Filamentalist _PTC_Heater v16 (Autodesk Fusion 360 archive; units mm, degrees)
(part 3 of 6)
sketch "Sketch166" plane through (-12.9087, 0, 0) normal (-1, 0, 0) x axis (0, -1, 0)
  line L1 (-124.3873, 24.4213) -> (-76.1273, 24.4213)
  line L2 (-124.3873, 53.6313) -> (-124.3873, 24.4213)
  line L3 (-76.1273, 53.6313) -> (-124.3873, 53.6313)
  line L4 (-76.1273, 24.4213) -> (-76.1273, 53.6313)
  line L5 (-72.0887, 73.7538) -> (-72.0887, -226.7462)
  line L6 (-127.2387, 73.7538) -> (-72.0887, 73.7538)
  line L7 (-127.2387, -226.7462) -> (-127.2387, 73.7538)
  line L8 (-72.0887, -226.7462) -> (-127.2387, -226.7462)
  curve K1 (-89.2728, -182.9578) -> (-90.2131, -183.7393)
  line L9 (-87.8074, -183.1531) -> (-89.2728, -182.9578)
  curve K2 (-90.21, -184.8139) -> (-87.8074, -183.1531)
  curve K3 (-92.341, -183.8736) -> (-90.21, -184.8139)
  curve K4 (-92.8874, -181.9732) -> (-92.341, -183.8736)
  curve K5 (-90.3459, -179.0501) -> (-92.8874, -181.9732)
  curve K6 (-87.7097, -182.3716) -> (-90.3459, -179.0501)
  line L10 (-91.422, -182.3716) -> (-87.7097, -182.3716)
  curve K7 (-90.2131, -183.7393) -> (-91.422, -182.3716)
  curve K8 (-107.639, -181.8541) -> (-104.8013, -184.8139)
  curve K9 (-104.8105, -179.0501) -> (-107.639, -181.8541)
  curve K10 (-101.9728, -181.9167) -> (-104.8105, -179.0501)
  curve K11 (-104.8013, -184.8139) -> (-101.9728, -181.9167)
  line L11 (-84.5836, -127.5662) -> (-84.5836, -125.9146)
  line L12 (-86.049, -127.5662) -> (-84.5836, -127.5662)
  line L13 (-86.049, -121.9978) -> (-86.049, -127.5662)
  line L14 (-84.5836, -121.9978) -> (-86.049, -121.9978)
  line L15 (-84.5836, -122.7747) -> (-84.5836, -121.9978)
  curve K12 (-83.4769, -121.9001) -> (-84.5836, -122.7747)
  curve K13 (-82.6297, -122.2084) -> (-83.4769, -121.9001)
  line L16 (-82.9717, -123.6021) -> (-82.6297, -122.2084)
  curve K14 (-83.6372, -123.3655) -> (-82.9717, -123.6021)
  curve K15 (-84.5836, -125.9146) -> (-83.6372, -123.3655)
  line L17 (-92.7897, -121.9978) -> (-93.8644, -121.9978)
  line L18 (-92.7897, -123.0724) -> (-92.7897, -121.9978)
  line L19 (-93.8644, -123.0724) -> (-92.7897, -123.0724)
  line L20 (-93.8644, -125.4658) -> (-93.8644, -123.0724)
  curve K16 (-93.4461, -126.5893) -> (-93.8644, -125.4658)
  curve K17 (-92.8386, -126.4489) -> (-93.4461, -126.5893)
  line L21 (-92.692, -127.4701) -> (-92.8386, -126.4489)
  curve K18 (-93.8705, -127.6639) -> (-92.692, -127.4701)
  curve K19 (-95.2824, -126.5939) -> (-93.8705, -127.6639)
  curve K20 (-95.3297, -125.5391) -> (-95.2824, -126.5939)
  line L22 (-95.3297, -123.0724) -> (-95.3297, -125.5391)
  line L23 (-96.0136, -123.0724) -> (-95.3297, -123.0724)
  line L24 (-96.0136, -121.9978) -> (-96.0136, -123.0724)
  line L25 (-95.3297, -121.9978) -> (-96.0136, -121.9978)
  line L26 (-95.3297, -120.9231) -> (-95.3297, -121.9978)
  line L27 (-93.8644, -120.0439) -> (-95.3297, -120.9231)
  line L28 (-93.8644, -121.9978) -> (-93.8644, -120.0439)
  curve K21 (-104.0244, -125.8078) -> (-104.9646, -126.5893)
  line L29 (-102.559, -126.0031) -> (-104.0244, -125.8078)
  curve K22 (-104.9616, -127.6639) -> (-102.559, -126.0031)
  curve K23 (-107.0925, -126.7236) -> (-104.9616, -127.6639)
  curve K24 (-107.639, -124.8232) -> (-107.0925, -126.7236)
  curve K25 (-105.0974, -121.9001) -> (-107.639, -124.8232)
  curve K26 (-102.4613, -125.2216) -> (-105.0974, -121.9001)
  line L30 (-106.1736, -125.2216) -> (-102.4613, -125.2216)
  curve K27 (-104.9646, -126.5893) -> (-106.1736, -125.2216)
  line L31 (-114.7705, -127.5662) -> (-113.3051, -127.5662)
  line L32 (-114.7705, -119.9462) -> (-114.7705, -127.5662)
  line L33 (-113.3051, -119.9462) -> (-114.7705, -119.9462)
  line L34 (-113.3051, -122.9747) -> (-113.3051, -119.9462)
  line L35 (-110.179, -122.9747) -> (-113.3051, -122.9747)
  line L36 (-110.179, -119.9462) -> (-110.179, -122.9747)
  line L37 (-108.7136, -119.9462) -> (-110.179, -119.9462)
  line L38 (-108.7136, -127.5662) -> (-108.7136, -119.9462)
  line L39 (-110.179, -127.5662) -> (-108.7136, -127.5662)
  line L40 (-110.179, -124.2447) -> (-110.179, -127.5662)
  line L41 (-113.3051, -124.2447) -> (-110.179, -124.2447)
  line L42 (-113.3051, -127.5662) -> (-113.3051, -124.2447)
  curve K28 (-100.312, -123.6585) -> (-99.3992, -122.9747)
  line L43 (-101.582, -123.4631) -> (-100.312, -123.6585)
  curve K29 (-99.2527, -121.9001) -> (-101.582, -123.4631)
  curve K30 (-96.9905, -124.034) -> (-99.2527, -121.9001)
  line L44 (-96.9905, -125.7452) -> (-96.9905, -124.034)
  curve K31 (-96.5997, -127.5662) -> (-96.9905, -125.7452)
  line L45 (-98.0651, -127.5662) -> (-96.5997, -127.5662)
  curve K32 (-98.204, -127.0991) -> (-98.0651, -127.5662)
  curve K33 (-98.2559, -126.9144) -> (-98.204, -127.0991)
  curve K34 (-99.9549, -127.6639) -> (-98.2559, -126.9144)
  curve K35 (-101.7774, -125.9955) -> (-99.9549, -127.6639)
  curve K36 (-99.8297, -124.2203) -> (-101.7774, -125.9955)
  curve K37 (-98.4559, -123.8539) -> (-99.8297, -124.2203)
  line L46 (-98.4559, -123.715) -> (-98.4559, -123.8539)
  curve K38 (-99.3992, -122.9747) -> (-98.4559, -123.715)
  curve K39 (-88.7844, -125.8078) -> (-89.7246, -126.5893)
  line L47 (-87.319, -126.0031) -> (-88.7844, -125.8078)
  curve K40 (-89.7216, -127.6639) -> (-87.319, -126.0031)
  curve K41 (-91.8525, -126.7236) -> (-89.7216, -127.6639)
  curve K42 (-92.399, -124.8232) -> (-91.8525, -126.7236)
  curve K43 (-89.8574, -121.9001) -> (-92.399, -124.8232)
  curve K44 (-87.2213, -125.2216) -> (-89.8574, -121.9001)
  line L48 (-90.9336, -125.2216) -> (-87.2213, -125.2216)
  curve K45 (-89.7246, -126.5893) -> (-90.9336, -125.2216)
  line L49 (-114.282, -184.7162) -> (-112.8167, -184.7162)
  line L50 (-114.282, -177.0962) -> (-114.282, -184.7162)
  line L51 (-111.8443, -177.0962) -> (-114.282, -177.0962)
  curve K46 (-110.037, -177.2122) -> (-111.8443, -177.0962)
  curve K47 (-108.5182, -179.4607) -> (-110.037, -177.2122)
  curve K48 (-110.2171, -181.7732) -> (-108.5182, -179.4607)
  curve K49 (-111.8138, -181.8831) -> (-110.2171, -181.7732)
  line L52 (-112.8167, -181.8831) -> (-111.8138, -181.8831)
  line L53 (-112.8167, -184.7162) -> (-112.8167, -181.8831)
  line L54 (-99.8083, -184.7162) -> (-98.3735, -184.7162)
  line L55 (-101.582, -179.1478) -> (-99.8083, -184.7162)
  line L56 (-100.1411, -179.1478) -> (-101.582, -179.1478)
  line L57 (-99.0909, -182.7975) -> (-100.1411, -179.1478)
  line L58 (-98.1323, -179.1478) -> (-99.0909, -182.7975)
  line L59 (-96.7051, -179.1478) -> (-98.1323, -179.1478)
  line L60 (-95.7694, -182.7975) -> (-96.7051, -179.1478)
  line L61 (-94.7161, -179.1478) -> (-95.7694, -182.7975)
  line L62 (-93.2782, -179.1478) -> (-94.7161, -179.1478)
  line L63 (-95.0473, -184.7162) -> (-93.2782, -179.1478)
  line L64 (-96.4624, -184.7162) -> (-95.0473, -184.7162)
  line L65 (-97.4301, -181.1352) -> (-96.4624, -184.7162)
  line L66 (-98.3735, -184.7162) -> (-97.4301, -181.1352)
  line L67 (-85.072, -184.7162) -> (-85.072, -183.0646)
  line L68 (-86.5374, -184.7162) -> (-85.072, -184.7162)
  line L69 (-86.5374, -179.1478) -> (-86.5374, -184.7162)
  line L70 (-85.072, -179.1478) -> (-86.5374, -179.1478)
  line L71 (-85.072, -179.9247) -> (-85.072, -179.1478)
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  point P98 (-114.282, -184.7162)
  point P130 (-114.282, -184.7162)
  point P133 (-114.282, -70)
  coincident P98 P130
  coincident P133
  dimension "d521" Text1-Height = 9
extrude "Extrude53" new body sketch "Sketch166" along normal blind 0.5
move "Move16"
sketch "Sketch167" plane through (-13.4087, 0, 0) normal (-1, 0, 0) x axis (0, -1, 0)
  line L1 (-107.8677, -67.4885) -> (-114.2033, -67.4885)
  line L2 (-107.8677, -65.9722) -> (-107.8677, -67.4885)
  line L3 (-112.3861, -65.9722) -> (-107.8677, -65.9722)
  line L4 (-112.3861, -58.5622) -> (-112.3861, -65.9722)
  line L5 (-114.2033, -58.5622) -> (-112.3861, -58.5622)
  line L6 (-114.2033, -67.4885) -> (-114.2033, -58.5622)
extrude "Extrude54" cut sketch "Sketch167" against normal blind 1
component_insert "Component Insert17"
position "Position9"
sketch "Sketch168" plane through (0, 131.7787, 0) normal (0, 1, 0) x axis (-1, 0, 0)
  line L1 (-118.8314, -119.7) -> (-123.5512, -119.7)
  line L2 (-126.1913, -226.7462) -> (-126.1913, -119.7)
  line L3 (5.4087, -246.7462) -> (-106.1913, -246.7462)
  line L4 (25.4087, -119.7) -> (25.4087, -226.7462)
  line L5 (25.409, -119.7) -> (25.4087, -119.7)
  line L6 (25.409, 4.05) -> (25.409, -119.7)
  line L7 (25.4087, 4.05) -> (25.409, 4.05)
  line L8 (25.4087, 82.7538) -> (25.4087, 4.05)
  line L9 (-106.3913, 102.7538) -> (5.4087, 102.7538)
  line L10 (-126.3913, 41.3578) -> (-126.3913, 82.7538)
  line L11 (-126.1913, 41.3578) -> (-126.3913, 41.3578)
  line L12 (-126.1913, 4.05) -> (-126.1913, 41.3578)
  line L13 (-126.1916, 4.05) -> (-126.1913, 4.05)
  line L14 (-126.1916, -119.7) -> (-126.1916, 4.05)
  line L15 (-126.1913, -119.7) -> (-126.1916, -119.7)
  line L16 (22.7686, -119.7) -> (18.0488, -119.7)
  line L17 (-123.4187, 4.05) -> (-118.964, 4.05)
  line L18 (-76.1597, 56.4579) -> (-80.4032, 60.7014)
  line L19 (-80.4031, 22.0143) -> (-76.1597, 26.2578)
  line L20 (-88, 44.8573) -> (-88, 37.8584)
  line L21 (-54.4515, 36.1073) -> (-50.2044, 31.8602)
  line L22 (-50.2044, 50.8555) -> (-54.4515, 46.6084)
  line L23 (-70.5577, 30.5022) -> (-74.8019, 26.258)
  line L24 (-45.9598, 26.258) -> (-50.204, 30.5022)
  line L25 (-49.5252, 31.181) -> (-45.281, 26.9368)
  line L26 (-45.2809, 55.779) -> (-49.5252, 51.5347)
  line L27 (-55.8105, 36.1087) -> (-60.3808, 40.6791)
  line L28 (-60.3808, 40.6791) -> (-64.9512, 36.1087)
  line L29 (-74.802, 56.4578) -> (-70.5577, 52.2135)
  line L30 (-50.204, 52.2135) -> (-45.9597, 56.4578)
  line L31 (-45.2808, 57.1367) -> (-41.0373, 61.3802)
  line L32 (-79.7244, 61.3802) -> (-75.4809, 57.1367)
  line L33 (-64.9512, 46.607) -> (-60.3808, 42.0366)
  line L34 (-60.3808, 42.0366) -> (-55.8105, 46.607)
  line L35 (-69.8785, 51.5343) -> (-65.6314, 47.2872)
  line L36 (-55.1303, 47.2872) -> (-50.8832, 51.5343)
  line L37 (-65.63, 36.7875) -> (-61.0596, 41.3578)
  line L38 (-61.0596, 41.3578) -> (-65.63, 45.9282)
  line L39 (-70.5573, 31.8602) -> (-66.3102, 36.1073)
  line L40 (-66.3102, 46.6084) -> (-70.5573, 50.8555)
  line L41 (-55.1317, 45.9282) -> (-59.7021, 41.3578)
  line L42 (-59.7021, 41.3578) -> (-55.1317, 36.7875)
  line L43 (-65.6314, 35.4285) -> (-69.8785, 31.1814)
  line L44 (-50.8832, 31.1814) -> (-55.1303, 35.4285)
  line L45 (-41.0373, 21.3355) -> (-45.2808, 25.579)
  line L46 (-75.4809, 25.579) -> (-79.7243, 21.3355)
  line L47 (-40.3585, 60.7014) -> (-44.602, 56.4579)
  line L48 (-44.602, 26.2578) -> (-40.3585, 22.0143)
  line L49 (-75.4807, 26.9368) -> (-71.2365, 31.181)
  line L50 (-71.2365, 51.5347) -> (-75.4808, 55.779)
  line L51 (18.1813, 4.05) -> (22.636, 4.05)
  line L52 (-32.5409, 15) -> (-32, 15)
  line L53 (-32.5409, 100.3238) -> (-32.5409, 15)
  line L54 (-32, 100.3238) -> (-32.5409, 100.3238)
  line L55 (-32, 15) -> (-32, 100.3238)
  line L56 (-32.2704, 100.3238) -> (-32, 100.3238)
  line L57 (-32, -299.6762) -> (-32.2704, -299.6762)
  line L58 (-30.6504, -149.5163) -> (-30.6504, -150.0451)
  line L59 (-30.5504, -290) -> (-30.5504, -150.0451)
  line L60 (-30.6504, -290) -> (-30.5504, -290)
  line L61 (-30.6504, -150.0451) -> (-30.6504, -290)
  line L62 (-32, -146.3811) -> (-32, -204.0447)
  line L63 (-32, 100.3238) -> (-32, 15)
  line L64 (-32.2704, 15) -> (-32.2704, 100.3238)
  line L65 (-32.2704, -204.2986) -> (-32.2704, -146.118)
  line L66 (-30.6504, -150.0451) -> (-30.5504, -150.0451)
  line L67 (-30.6504, 249.9549) -> (-30.6504, -150.0451)
  line L68 (-30.5504, 249.9549) -> (-30.6504, 249.9549)
  line L69 (-30.5504, -150.0451) -> (-30.5504, 249.9549)
  arc A1 centre (-121.1913, -120.7912) radius 2.6 clockwise from (-118.8314, -119.7) to (-123.5512, -119.7)
  arc A2 centre (-106.1913, -226.7462) radius 20 clockwise from (-106.1913, -246.7462) to (-126.1913, -226.7462)
  arc A3 centre (5.4087, -226.7462) radius 20 clockwise from (25.4087, -226.7462) to (5.4087, -246.7462)
  arc A4 centre (5.4087, 82.7538) radius 20 clockwise from (5.4087, 102.7538) to (25.4087, 82.7538)
  arc A5 centre (-106.3913, 82.7538) radius 20 clockwise from (-126.3913, 82.7538) to (-106.3913, 102.7538)
  circle C1 centre (-49.7433, -184.0812) radius 3.175
  circle C2 centre (-42.0443, -179.6362) radius 3.175
  circle C3 centre (-34.3453, -166.3012) radius 3.175
  circle C4 centre (-11.2484, -224.0862) radius 3.175
  circle C5 centre (-18.9474, -175.1912) radius 3.175
  circle C6 centre (-26.6464, -170.7462) radius 3.175
  circle C7 centre (-26.6464, -161.8562) radius 3.175
  circle C8 centre (-3.5495, -192.9712) radius 3.175
  circle C9 centre (-3.5495, -184.0812) radius 3.175
  circle C10 centre (-18.9474, -184.0812) radius 3.175
  circle C11 centre (-11.2484, -188.5262) radius 3.175
  circle C12 centre (-11.2484, -197.4162) radius 3.175
  circle C13 centre (-3.5495, -201.8612) radius 3.175
  circle C14 centre (-3.5495, -157.4112) radius 3.175
  circle C15 centre (-18.9474, -148.5212) radius 3.175
  circle C16 centre (-11.2484, -152.9662) radius 3.175
  circle C17 centre (-11.2484, -161.8562) radius 3.175
  circle C18 centre (-3.5495, -148.5212) radius 3.175
  circle C19 centre (-11.2484, -144.0762) radius 3.175
  circle C20 centre (-11.2484, -179.6362) radius 3.175
  circle C21 centre (-11.2484, -170.7462) radius 3.175
  circle C22 centre (-18.9474, -166.3012) radius 3.175
  circle C23 centre (-18.9474, -157.4112) radius 3.175
  circle C24 centre (-3.5495, -175.1912) radius 3.175
  circle C25 centre (-3.5495, -166.3012) radius 3.175
  arc A6 centre (-26.6058, -206.3059) radius 3.175 clockwise from (-26.65, -203.1312) to (-26.6021, -209.4809)
  arc A7 centre (-26.6464, -206.3062) radius 3.175 clockwise from (-26.6021, -209.4809) to (-26.65, -203.1312)
  arc A8 centre (-18.9068, -210.7509) radius 3.175 clockwise from (-18.9511, -207.5762) to (-18.9032, -213.9259)
  arc A9 centre (-18.9474, -210.7512) radius 3.175 clockwise from (-18.9032, -213.9259) to (-18.9511, -207.5762)
  circle C26 centre (-11.2484, -215.1962) radius 3.175
  circle C27 centre (-3.5495, -219.6412) radius 3.175
  circle C28 centre (-42.0443, -188.5262) radius 3.175
  circle C29 centre (-42.0443, -197.4162) radius 3.175
  arc A10 centre (-34.3047, -201.8609) radius 3.175 clockwise from (-34.349, -198.6862) to (-34.3011, -205.0359)
  arc A11 centre (-34.3453, -201.8612) radius 3.175 clockwise from (-34.3011, -205.0359) to (-34.349, -198.6862)
  circle C30 centre (-34.3453, -210.7512) radius 3.175
  arc A12 centre (-26.6058, -215.1959) radius 3.175 clockwise from (-26.65, -212.0212) to (-26.6021, -218.3709)
  arc A13 centre (-26.6464, -215.1962) radius 3.175 clockwise from (-26.6021, -218.3709) to (-26.65, -212.0212)
  circle C31 centre (-18.9474, -219.6412) radius 3.175
  circle C32 centre (-18.9474, -201.8612) radius 3.175
  circle C33 centre (-11.2484, -206.3062) radius 3.175
  circle C34 centre (-3.5495, -210.7512) radius 3.175
  circle C35 centre (-18.9474, -192.9712) radius 3.175
  circle C36 centre (-26.6464, -188.5262) radius 3.175
  circle C37 centre (-26.6464, -179.6362) radius 3.175
  arc A14 centre (-34.3089, -175.1909) radius 3.175 clockwise from (-34.3538, -172.0162) to (-34.3004, -178.3659)
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  point P289 (-32, -204.0447)
  point P290 (-32.2704, -204.2986)
  point P292 (-32.2704, 15)
  point P280 (-32, 100.3238)
  point P283 (-32, -299.6762)
  point P285 (-30.6504, -150.0451)
  point P286 (-30.5504, -150.0451)
  point P296 (-30.5504, 249.9549)
  horizontal L52
  vertical L53
  horizontal L54
  vertical L55
  horizontal L56
  vertical L64
  horizontal L57
  vertical L58
  vertical L59
  horizontal L60
  vertical L61
  coincident A10 P289
  coincident A10 P290
  collinear L62 L63
  coincident L52 P292
  collinear L64 L65
  horizontal L66
  vertical L67
  horizontal L68
  vertical L69
  dimension "d529" distance P280 P283 = 400
  dimension "d530" distance P285 P286 = 0.1
  dimension "d531" distance P286 P296 = 400
extrude "Extrude38" cut sketch "Sketch168" profile of L3 L9 L58 L59 L60 L61 L66 L67 L68 L69 against normal blind 150
move "Move3"
sketch "Sketch169" plane through (0, 129.2387, 0) normal (0, -1, 0) x axis (1, 0, 0)
  line L1 (30.6504, -231.7062) -> (30.6504, 78.7138)
  line L2 (106.1913, -231.7062) -> (30.6504, -231.7062)
  line L3 (111.1513, 73.7538) -> (111.1513, -226.7462)
  line L4 (30.6504, 78.7138) -> (106.1913, 78.7138)
  line L5 (76.1597, 26.2578) -> (80.4031, 22.0143)
  line L6 (80.4032, 60.7014) -> (76.1597, 56.4579)
  line L7 (88, 37.8584) -> (88, 44.8573)
  line L8 (50.2044, 31.8602) -> (54.4515, 36.1073)
  line L9 (54.4515, 46.6084) -> (50.2044, 50.8555)
  line L10 (74.8019, 26.258) -> (70.5577, 30.5022)
  line L11 (50.204, 30.5022) -> (45.9598, 26.258)
  line L12 (45.281, 26.9368) -> (49.5252, 31.181)
  line L13 (49.5252, 51.5347) -> (45.2809, 55.779)
  line L14 (60.3808, 40.6791) -> (55.8105, 36.1087)
  line L15 (64.9512, 36.1087) -> (60.3808, 40.6791)
  line L16 (70.5577, 52.2135) -> (74.802, 56.4578)
  line L17 (45.9597, 56.4578) -> (50.204, 52.2135)
  line L18 (41.0373, 61.3802) -> (45.2808, 57.1367)
  line L19 (75.4809, 57.1367) -> (79.7244, 61.3802)
  line L20 (60.3808, 42.0366) -> (64.9512, 46.607)
  line L21 (55.8105, 46.607) -> (60.3808, 42.0366)
  line L22 (65.6314, 47.2872) -> (69.8785, 51.5343)
  line L23 (50.8832, 51.5343) -> (55.1303, 47.2872)
  line L24 (61.0596, 41.3578) -> (65.63, 36.7875)
  line L25 (65.63, 45.9282) -> (61.0596, 41.3578)
  line L26 (66.3102, 36.1073) -> (70.5573, 31.8602)
  line L27 (70.5573, 50.8555) -> (66.3102, 46.6084)
  line L28 (59.7021, 41.3578) -> (55.1317, 45.9282)
  line L29 (55.1317, 36.7875) -> (59.7021, 41.3578)
  line L30 (69.8785, 31.1814) -> (65.6314, 35.4285)
  line L31 (55.1303, 35.4285) -> (50.8832, 31.1814)
  line L32 (45.2808, 25.579) -> (41.0373, 21.3355)
  line L33 (79.7243, 21.3355) -> (75.4809, 25.579)
  line L34 (44.602, 56.4579) -> (40.3585, 60.7014)
  line L35 (40.3585, 22.0143) -> (44.602, 26.2578)
  line L36 (71.2365, 31.181) -> (75.4807, 26.9368)
  line L37 (75.4808, 55.779) -> (71.2365, 51.5347)
  line L38 (61.4013, -137.5996) -> (30.6504, -137.5996)
  line L39 (61.4013, -230.2494) -> (61.4013, -137.5996)
  line L40 (30.6504, -230.2494) -> (61.4013, -230.2494)
  line L41 (30.6504, -137.5996) -> (30.6504, -230.2494)
  circle C1 centre (34.3453, -192.9712) radius 3.175
  circle C2 centre (34.3453, -210.7512) radius 3.175
  circle C3 centre (42.0443, -197.4162) radius 3.175
  circle C4 centre (42.0443, -188.5262) radius 3.175
  circle C5 centre (49.7433, -166.3012) radius 3.175
  circle C6 centre (49.7433, -175.1912) radius 3.175
  circle C7 centre (57.4422, -170.7462) radius 3.175
  circle C8 centre (57.4422, -161.8562) radius 3.175
  circle C9 centre (65.1412, -157.4112) radius 3.175
  circle C10 centre (65.1412, -148.5212) radius 3.175
  circle C11 centre (42.0443, -152.9662) radius 3.175
  circle C12 centre (42.0443, -144.0762) radius 3.175
  circle C13 centre (34.3453, -148.5212) radius 3.175
  circle C14 centre (34.3453, -157.4112) radius 3.175
  circle C15 centre (49.7433, -184.0812) radius 3.175
  circle C16 centre (34.3453, -166.3012) radius 3.175
  circle C17 centre (42.0443, -179.6362) radius 3.175
  arc A1 centre (34.3047, -201.8609) radius 3.175 clockwise from (34.3011, -205.0359) to (34.349, -198.6862)
  arc A2 centre (34.3453, -201.8612) radius 3.175 clockwise from (34.349, -198.6862) to (34.3011, -205.0359)
  arc A3 centre (34.3089, -184.0809) radius 3.175 clockwise from (34.3004, -187.2559) to (34.3538, -180.9062)
  arc A4 centre (34.3453, -184.0812) radius 3.175 clockwise from (34.3538, -180.9062) to (34.3004, -187.2559)
  arc A5 centre (34.3089, -175.1909) radius 3.175 clockwise from (34.3004, -178.3659) to (34.3538, -172.0162)
  arc A6 centre (34.3453, -175.1912) radius 3.175 clockwise from (34.3538, -172.0162) to (34.3004, -178.3659)
  arc A7 centre (42.0078, -170.7459) radius 3.175 clockwise from (41.9994, -173.9209) to (42.0527, -167.5712)
  arc A8 centre (42.0443, -170.7462) radius 3.175 clockwise from (42.0527, -167.5712) to (41.9994, -173.9209)
  arc A9 centre (42.0078, -161.8559) radius 3.175 clockwise from (41.9994, -165.0309) to (42.0527, -158.6812)
  arc A10 centre (42.0443, -161.8562) radius 3.175 clockwise from (42.0527, -158.6812) to (41.9994, -165.0309)
  arc A11 centre (49.7068, -148.5209) radius 3.175 clockwise from (49.6984, -151.6959) to (49.7517, -145.3462)
  arc A12 centre (49.7433, -148.5212) radius 3.175 clockwise from (49.7517, -145.3462) to (49.6984, -151.6959)
  arc A13 centre (57.4058, -144.0759) radius 3.175 clockwise from (57.3973, -147.2509) to (57.4507, -140.9012)
  arc A14 centre (57.4422, -144.0762) radius 3.175 clockwise from (57.4507, -140.9012) to (57.3973, -147.2509)
  arc A15 centre (57.4058, -152.9659) radius 3.175 clockwise from (57.3973, -156.1409) to (57.4507, -149.7912)
  arc A16 centre (57.4422, -152.9662) radius 3.175 clockwise from (57.4507, -149.7912) to (57.3973, -156.1409)
  arc A17 centre (49.7068, -157.4109) radius 3.175 clockwise from (49.6984, -160.5859) to (49.7517, -154.2362)
  arc A18 centre (49.7433, -157.4112) radius 3.175 clockwise from (49.7517, -154.2362) to (49.6984, -160.5859)
  circle C18 centre (88.2342, -224.0862) radius 3.175
  circle C19 centre (95.9332, -219.6412) radius 3.175
  circle C20 centre (95.9332, -210.7512) radius 3.175
  circle C21 centre (88.2342, -215.1962) radius 3.175
  circle C22 centre (80.5027, -219.6409) radius 3.175
  circle C23 centre (72.8037, -224.0859) radius 3.175
  circle C24 centre (95.9332, -201.8612) radius 3.175
  circle C25 centre (88.2342, -206.3062) radius 3.175
  circle C26 centre (65.1332, -219.6412) radius 3.175
  circle C27 centre (49.7027, -210.7509) radius 3.175
  circle C28 centre (49.7352, -201.8612) radius 3.175
  circle C29 centre (65.1332, -210.7512) radius 3.175
  circle C30 centre (72.8037, -197.4159) radius 3.175
  circle C31 centre (57.4058, -188.5259) radius 3.175
  circle C32 centre (57.4342, -197.4162) radius 3.175
  circle C33 centre (72.8037, -206.3059) radius 3.175
  circle C34 centre (80.5027, -201.8609) radius 3.175
  circle C35 centre (80.5027, -192.9709) radius 3.175
  circle C36 centre (65.1047, -184.0809) radius 3.175
  circle C37 centre (65.1047, -175.1909) radius 3.175
  circle C38 centre (80.5027, -184.0809) radius 3.175
  circle C39 centre (88.2342, -188.5262) radius 3.175
  circle C40 centre (88.2342, -179.6362) radius 3.175
  circle C41 centre (65.1047, -166.3009) radius 3.175
  circle C42 centre (80.5027, -175.1909) radius 3.175
  circle C43 centre (95.9332, -166.3012) radius 3.175
  circle C44 centre (72.8037, -161.8559) radius 3.175
  circle C45 centre (80.5027, -157.4109) radius 3.175
  circle C46 centre (95.9332, -157.4112) radius 3.175
  circle C47 centre (88.2342, -152.9662) radius 3.175
  circle C48 centre (88.2342, -144.0762) radius 3.175
  circle C49 centre (72.8037, -144.0759) radius 3.175
  circle C50 centre (80.5027, -148.5209) radius 3.175
  circle C51 centre (95.9332, -148.5212) radius 3.175
  circle C52 centre (88.2342, -161.8562) radius 3.175
  circle C53 centre (72.8037, -152.9659) radius 3.175
  circle C54 centre (80.5027, -166.3009) radius 3.175
  circle C55 centre (88.2342, -170.7462) radius 3.175
  circle C56 centre (72.8037, -170.7459) radius 3.175
  circle C57 centre (95.9332, -184.0812) radius 3.175
  circle C58 centre (95.9332, -175.1912) radius 3.175
  circle C59 centre (95.9332, -192.9712) radius 3.175
  circle C60 centre (72.8037, -179.6359) radius 3.175
  circle C61 centre (57.4058, -179.6359) radius 3.175
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  point P195 (30.6504, -137.5996)
  horizontal L38
  vertical L39
  horizontal L40
  vertical L41
  coincident L1 P195
extrude "Extrude55" new body sketch "Sketch169" along normal blind 1
move "Move17"
copy_paste_bodies "CopyPasteBodies6"
move "Move18"
move "Move4"
move "Move5"
position "Position10"
combine "Combine5"
sketch "Sketch170" plane through (15.1204, 0, 0) normal (1, 0, 0) x axis (0, 1, 0)
  line L1 (127.2387, 102.7538) -> (131.7787, 102.7538)
  line L2 (127.2387, 81.2538) -> (127.2387, 102.7538)
  line L3 (72.0887, 81.2538) -> (127.2387, 81.2538)
  line L4 (72.0887, 78.9678) -> (72.0887, 81.2538)
  line L5 (74.3239, 78.9678) -> (72.0887, 78.9678)
  line L6 (74.3239, 77.8502) -> (74.3239, 78.9678)
  line L7 (84.4331, 77.8502) -> (74.3239, 77.8502)
  line L8 (85.2967, 78.7138) -> (84.4331, 77.8502)
  line L9 (129.2387, 78.7138) -> (85.2967, 78.7138)
  line L10 (129.2387, -231.7062) -> (129.2387, 78.7138)
  line L11 (85.2967, -231.7062) -> (129.2387, -231.7062)
  line L12 (84.4331, -230.8426) -> (85.2967, -231.7062)
  line L13 (74.3239, -230.8426) -> (84.4331, -230.8426)
  line L14 (74.3239, -231.9602) -> (74.3239, -230.8426)
  line L15 (72.0887, -231.9602) -> (74.3239, -231.9602)
  line L16 (72.0887, -234.2462) -> (72.0887, -231.9602)
  line L17 (127.2387, -234.2462) -> (72.0887, -234.2462)
  line L18 (127.2387, -246.7462) -> (127.2387, -234.2462)
  line L19 (131.7787, -246.7462) -> (127.2387, -246.7462)
  line L20 (131.7787, 102.7538) -> (131.7787, -246.7462)
extrude "Extrude39" add sketch "Sketch170" along normal blind 15.53
sketch "Sketch171" plane through (0, 128.2387, 0) normal (0, -1, 0) x axis (1, 0, 0)
  line L1 (-0.2096, -137.5996) -> (45.9713, -137.5996)
  line L2 (-0.2096, -230.2494) -> (-0.2096, -137.5996)
  line L3 (45.9713, -230.2494) -> (-0.2096, -230.2494)
  line L4 (45.9713, -137.5996) -> (45.9713, -230.2494)
  circle C1 centre (41.9758, -188.5259) radius 3.175
  circle C2 centre (34.2768, -192.9709) radius 3.175
  circle C3 centre (34.3133, -166.3012) radius 3.175
  circle C4 centre (42.0042, -197.4162) radius 3.175
  circle C5 centre (34.3133, -175.1912) radius 3.175
  circle C6 centre (42.0122, -170.7462) radius 3.175
  circle C7 centre (42.0042, -215.1962) radius 3.175
  circle C8 centre (34.3052, -201.8612) radius 3.175
  arc A1 centre (42.0122, -152.9662) radius 3.175 clockwise from (42.0207, -149.7912) to (41.9673, -156.1409)
  arc A2 centre (41.9758, -152.9659) radius 3.175 clockwise from (41.9673, -156.1409) to (42.0207, -149.7912)
  circle C9 centre (34.3133, -184.0812) radius 3.175
  circle C10 centre (41.9758, -179.6359) radius 3.175
  arc A3 centre (34.3133, -157.4112) radius 3.175 clockwise from (34.3217, -154.2362) to (34.2684, -160.5859)
  arc A4 centre (34.2768, -157.4109) radius 3.175 clockwise from (34.2684, -160.5859) to (34.3217, -154.2362)
  arc A5 centre (34.3133, -148.5212) radius 3.175 clockwise from (34.3217, -145.3462) to (34.2684, -151.6959)
  arc A6 centre (34.2768, -148.5209) radius 3.175 clockwise from (34.2684, -151.6959) to (34.3217, -145.3462)
  circle C11 centre (42.0042, -206.3062) radius 3.175
  circle C12 centre (42.0042, -224.0862) radius 3.175
  circle C13 centre (42.0122, -161.8562) radius 3.175
  arc A7 centre (42.0122, -144.0762) radius 3.175 clockwise from (42.0207, -140.9012) to (41.9673, -147.2509)
  arc A8 centre (41.9758, -144.0759) radius 3.175 clockwise from (41.9673, -147.2509) to (42.0207, -140.9012)
  circle C14 centre (34.3052, -219.6412) radius 3.175
  circle C15 centre (34.2727, -210.7509) radius 3.175
  arc A9 centre (26.5822, -144.0762) radius 3.175 clockwise from (26.5983, -140.9013) to (26.5983, -147.2512)
  arc A10 centre (26.6143, -144.0762) radius 3.175 clockwise from (26.5983, -147.2512) to (26.5983, -140.9013)
  arc A11 centre (18.8833, -148.5212) radius 3.175 clockwise from (18.8993, -145.3463) to (18.8993, -151.6962)
  arc A12 centre (18.9153, -148.5212) radius 3.175 clockwise from (18.8993, -151.6962) to (18.8993, -145.3463)
  arc A13 centre (18.8833, -157.4112) radius 3.175 clockwise from (18.8993, -154.2363) to (18.8993, -160.5862)
  arc A14 centre (18.9153, -157.4112) radius 3.175 clockwise from (18.8993, -160.5862) to (18.8993, -154.2363)
  arc A15 centre (26.5822, -152.9662) radius 3.175 clockwise from (26.5983, -149.7913) to (26.5983, -156.1412)
  arc A16 centre (26.6143, -152.9662) radius 3.175 clockwise from (26.5983, -156.1412) to (26.5983, -149.7913)
  arc A17 centre (18.8833, -184.0812) radius 3.175 clockwise from (18.6596, -187.2483) to (18.8993, -187.2562)
  arc A18 centre (18.9153, -184.0812) radius 3.175 clockwise from (18.8993, -187.2562) to (18.8704, -187.2559)
  arc A19 centre (18.8789, -184.0809) radius 3.175 clockwise from (18.8704, -187.2559) to (18.6596, -187.2483)
  arc A20 centre (26.5458, -188.5259) radius 3.175 clockwise from (26.5942, -185.3513) to (26.5659, -191.7009)
  arc A21 centre (26.6143, -188.5262) radius 3.175 clockwise from (26.5659, -191.7009) to (26.5942, -185.3513)
  arc A22 centre (18.8833, -166.3012) radius 3.175 clockwise from (18.8993, -163.1263) to (18.8993, -169.4762)
  arc A23 centre (18.9153, -166.3012) radius 3.175 clockwise from (18.8993, -169.4762) to (18.8993, -163.1263)
  arc A24 centre (18.8752, -201.8612) radius 3.175 clockwise from (17.1714, -204.5403) to (18.8953, -205.0362)
  arc A25 centre (18.9153, -201.8612) radius 3.175 clockwise from (18.8953, -205.0362) to (18.8711, -205.0359)
  arc A26 centre (18.8747, -201.8609) radius 3.175 clockwise from (18.8711, -205.0359) to (17.1714, -204.5403)
  arc A27 centre (26.5742, -215.1962) radius 3.175 clockwise from (26.5902, -212.0213) to (26.5902, -218.3712)
  arc A28 centre (26.6063, -215.1962) radius 3.175 clockwise from (26.5902, -218.3712) to (26.5902, -212.0213)
  arc A29 centre (26.5822, -170.7462) radius 3.175 clockwise from (26.3586, -173.9133) to (26.5983, -173.9212)
  arc A30 centre (26.6143, -170.7462) radius 3.175 clockwise from (26.5983, -173.9212) to (26.5694, -173.9209)
  arc A31 centre (26.5778, -170.7459) radius 3.175 clockwise from (26.5694, -173.9209) to (26.3586, -173.9133)
  arc A32 centre (26.5742, -197.4162) radius 3.175 clockwise from (26.5942, -194.2413) to (26.5942, -200.5912)
  arc A33 centre (26.6143, -197.4162) radius 3.175 clockwise from (26.5942, -200.5912) to (26.5942, -194.2413)
  circle C16 centre (3.4853, -157.4112) radius 3.175
  arc A34 centre (3.4853, -175.1912) radius 3.175 clockwise from (3.4938, -172.0162) to (3.4404, -178.3659)
  arc A35 centre (3.4489, -175.1909) radius 3.175 clockwise from (3.4404, -178.3659) to (3.4938, -172.0162)
  circle C17 centre (11.1843, -197.4162) radius 3.175
  circle C18 centre (11.0742, -224.0862) radius 3.175
  arc A36 centre (11.1843, -170.7462) radius 3.175 clockwise from (11.1927, -167.5712) to (11.1394, -173.9209)
  arc A37 centre (11.1478, -170.7459) radius 3.175 clockwise from (11.1394, -173.9209) to (11.1927, -167.5712)
  circle C19 centre (3.4447, -219.6409) radius 3.175
  circle C20 centre (11.1763, -215.1962) radius 3.175
  circle C21 centre (11.1843, -179.6362) radius 3.175
  circle C22 centre (11.1843, -152.9662) radius 3.175
  arc A38 centre (3.4853, -201.8612) radius 3.175 clockwise from (3.489, -198.6862) to (3.4411, -205.0359)
  arc A39 centre (3.4447, -201.8609) radius 3.175 clockwise from (3.4411, -205.0359) to (3.489, -198.6862)
  circle C23 centre (3.4853, -210.7512) radius 3.175
  circle C24 centre (3.4853, -166.3012) radius 3.175
  circle C25 centre (11.1763, -206.3062) radius 3.175
  circle C26 centre (11.1843, -188.5262) radius 3.175
  circle C27 centre (3.4853, -192.9712) radius 3.175
  circle C28 centre (3.4853, -148.5212) radius 3.175
  circle C29 centre (11.1843, -144.0762) radius 3.175
  arc A40 centre (3.4853, -184.0812) radius 3.175 clockwise from (3.4938, -180.9062) to (3.4404, -187.2559)
  arc A41 centre (3.4489, -184.0809) radius 3.175 clockwise from (3.4404, -187.2559) to (3.4938, -180.9062)
  arc A42 centre (11.1843, -161.8562) radius 3.175 clockwise from (11.1927, -158.6812) to (11.1394, -165.0309)
  arc A43 centre (11.1478, -161.8559) radius 3.175 clockwise from (11.1394, -165.0309) to (11.1927, -158.6812)
  arc A44 centre (18.8833, -175.1912) radius 3.175 clockwise from (18.6596, -178.3583) to (18.8993, -178.3662)
  arc A45 centre (18.9153, -175.1912) radius 3.175 clockwise from (18.8993, -178.3662) to (18.8704, -178.3659)
  arc A46 centre (18.8789, -175.1909) radius 3.175 clockwise from (18.8704, -178.3659) to (18.6596, -178.3583)
  arc A47 centre (26.5742, -224.0862) radius 3.175 clockwise from (26.5392, -227.261) to (26.5392, -220.9114)
  arc A48 centre (26.5042, -224.0862) radius 3.175 clockwise from (26.5392, -220.9114) to (26.5392, -227.261)
  arc A49 centre (18.8752, -219.6412) radius 3.175 clockwise from (17.1714, -222.3203) to (20.5786, -216.9618)
  arc A50 centre (18.8747, -219.6409) radius 3.175 clockwise from (20.5786, -216.9618) to (17.1714, -222.3203)
  arc A51 centre (26.5458, -179.6359) radius 3.175 clockwise from (26.5942, -176.4613) to (26.5659, -182.8109)
  arc A52 centre (26.6143, -179.6362) radius 3.175 clockwise from (26.5659, -182.8109) to (26.5942, -176.4613)
  arc A53 centre (18.8427, -210.7509) radius 3.175 clockwise from (18.8924, -207.5763) to (18.8656, -213.9258)
  arc A54 centre (18.9153, -210.7512) radius 3.175 clockwise from (18.8656, -213.9258) to (18.8924, -207.5763)
  arc A55 centre (26.5742, -206.3062) radius 3.175 clockwise from (26.5902, -203.1313) to (26.5902, -209.4812)
  arc A56 centre (26.6063, -206.3062) radius 3.175 clockwise from (26.5902, -209.4812) to (26.5902, -203.1313)
  arc A57 centre (18.8468, -192.9709) radius 3.175 clockwise from (18.8953, -189.7963) to (18.8669, -196.1459)
  arc A58 centre (18.9153, -192.9712) radius 3.175 clockwise from (18.8669, -196.1459) to (18.8953, -189.7963)
  arc A59 centre (26.5822, -161.8562) radius 3.175 clockwise from (26.3586, -165.0233) to (26.5983, -165.0312)
  arc A60 centre (26.6143, -161.8562) radius 3.175 clockwise from (26.5983, -165.0312) to (26.5694, -165.0309)
  arc A61 centre (26.5778, -161.8559) radius 3.175 clockwise from (26.5694, -165.0309) to (26.3586, -165.0233)
extrude "Extrude40" cut sketch "Sketch171" profile of A9 A10 A11 A12 A13 A14 A15 A16 A17 A18 A19 A20 A21 A22 A23 A24 A25 A26 A27 A28 A29 A30 A31 A32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 against normal blind 50
delete_face "DeleteFace19"
delete_face "DeleteFace20"
delete_face "DeleteFace21"
delete_face "DeleteFace22"
remove_body "RemoveBody177"
remove_body "RemoveBody178"
remove_body "RemoveBody179"
remove_body "RemoveBody180"
remove_body "RemoveBody181"
remove_body "RemoveBody182"
move "Move4"
sketch "Sketch172" plane through (14.9867, 0, 0) normal (1, 0, 0) x axis (0, 1, 0)
  line L1 (71.9956, 78.611) -> (73.9768, 78.611)
  line L2 (71.9956, 81.151) -> (71.9956, 78.611)
  line L3 (70.9796, 81.151) -> (71.9956, 81.151)
  line L4 (69.9636, 80.135) -> (70.9796, 81.151)
  line L5 (69.9636, -233.333) -> (69.9636, 80.135)
  line L6 (70.9796, -234.349) -> (69.9636, -233.333)
  line L7 (71.9956, -234.349) -> (70.9796, -234.349)
  line L8 (71.9956, -231.809) -> (71.9956, -234.349)
  line L9 (73.9768, -231.809) -> (71.9956, -231.809)
  line L10 (73.9768, 78.611) -> (73.9768, -231.809)
extrude "Extrude3" add sketch "Sketch172" along normal blind 16
sketch "Sketch173" plane through (0, 127.2387, 0) normal (0, -1, 0) x axis (1, 0, 0)
  line L1 (106.3913, 81.2538) -> (-20.8387, 81.2538)
  line L2 (113.8913, -226.7462) -> (113.8913, 73.7538)
  line L3 (-20.8387, -234.2462) -> (106.3913, -234.2462)
  line L4 (-28.3387, 73.7538) -> (-28.3387, -226.7462)
  line L5 (-20.8387, 102.7538) -> (106.3913, 102.7538)
  line L6 (-40.8387, 4.05) -> (-40.8387, 82.7538)
  line L7 (-40.839, 4.05) -> (-40.8387, 4.05)
  line L8 (-40.839, -119.7) -> (-40.839, 4.05)
  line L9 (-40.8387, -119.7) -> (-40.839, -119.7)
  line L10 (-40.8387, -226.7462) -> (-40.8387, -119.7)
  line L11 (106.1913, -246.7462) -> (-20.8387, -246.7462)
  line L12 (126.1913, -119.7) -> (126.1913, -226.7462)
  line L13 (126.1916, -119.7) -> (126.1913, -119.7)
  line L14 (126.1916, 4.05) -> (126.1916, -119.7)
  line L15 (126.1913, 4.05) -> (126.1916, 4.05)
  line L16 (126.1913, 41.3578) -> (126.1913, 4.05)
  line L17 (126.3913, 41.3578) -> (126.1913, 41.3578)
  line L18 (126.3913, 82.7538) -> (126.3913, 41.3578)
  arc A1 centre (106.3913, 73.7538) radius 7.5 clockwise from (106.3913, 81.2538) to (113.8913, 73.7538)
  arc A2 centre (106.3913, -226.7462) radius 7.5 clockwise from (113.8913, -226.7462) to (106.3913, -234.2462)
  arc A3 centre (-20.8387, -226.7462) radius 7.5 clockwise from (-20.8387, -234.2462) to (-28.3387, -226.7462)
  arc A4 centre (-20.8387, 73.7538) radius 7.5 clockwise from (-28.3387, 73.7538) to (-20.8387, 81.2538)
  circle C1 centre (-35.8387, -120.7912) radius 2.6
  circle C2 centre (-35.8387, -200.7462) radius 2.6
  circle C3 centre (-12.0887, -241.6462) radius 2.6
  circle C4 centre (-20.0387, 88.3538) radius 2.6
  circle C5 centre (-35.8387, 2.7088) radius 2.6
  arc A5 centre (-20.8387, 73.7538) radius 29 clockwise from (-40.8387, 82.7538) to (-20.8387, 102.7538)
  arc A6 centre (-20.8387, -226.7462) radius 20 clockwise from (-20.8387, -246.7462) to (-40.8387, -226.7462)
  arc A7 centre (106.1913, -226.7462) radius 20 clockwise from (126.1913, -226.7462) to (106.1913, -246.7462)
  arc A8 centre (106.3913, 73.7538) radius 21.9317 clockwise from (106.3913, 102.7538) to (126.3913, 82.7538)
  circle C6 centre (121.1913, -120.7912) radius 2.6
  circle C7 centre (97.4413, -241.6462) radius 2.6
  circle C8 centre (121.1913, -200.7462) radius 2.6
  arc A9 centre (105.5913, 88.3538) radius 2.6 clockwise from (105.4913, 85.7557) to (105.4913, 90.9519)
  arc A10 centre (105.3913, 88.3538) radius 2.6 clockwise from (105.4913, 90.9519) to (105.4913, 85.7557)
  circle C9 centre (121.1913, 2.7088) radius 2.6
sketch "Sketch174" plane through (0, 74.3239, 0) normal (0, -1, 0) x axis (1, 0, 0)
  line L1 (102.2613, 77.8502) -> (-16.9087, 77.8502)
  line L2 (103.5313, 74.9038) -> (103.5313, 76.5802)
  line L3 (109.0177, 71.0938) -> (107.3413, 71.0938)
  line L4 (110.2877, -133.1662) -> (110.2877, 69.8238)
  line L5 (107.3413, -134.4362) -> (109.0177, -134.4362)
  line L6 (109.0177, -142.0562) -> (107.3413, -142.0562)
  line L7 (110.2877, -222.8162) -> (110.2877, -143.3262)
  line L8 (107.3413, -224.0862) -> (109.0177, -224.0862)
  line L9 (103.5313, -229.5726) -> (103.5313, -227.8962)
  line L10 (-16.9087, -230.8426) -> (102.2613, -230.8426)
  line L11 (-18.1787, -227.8962) -> (-18.1787, -229.5726)
  line L12 (-23.6651, -224.0862) -> (-21.9887, -224.0862)
  line L13 (-24.9351, -143.3262) -> (-24.9351, -222.8162)
  line L14 (-21.9887, -142.0562) -> (-23.6651, -142.0562)
  line L15 (-23.6651, -134.4362) -> (-21.9887, -134.4362)
  line L16 (-24.9351, 22.1988) -> (-24.9351, -133.1662)
  line L17 (-23.2587, 22.1988) -> (-24.9351, 22.1988)
  line L18 (-23.2587, 55.8538) -> (-23.2587, 22.1988)
  line L19 (-24.9351, 55.8538) -> (-23.2587, 55.8538)
  line L20 (-24.9351, 69.8238) -> (-24.9351, 55.8538)
  line L21 (-21.9887, 71.0938) -> (-23.6651, 71.0938)
  line L22 (-18.1787, 76.5802) -> (-18.1787, 74.9038)
  line L23 (-20.8387, 78.9678) -> (106.1913, 78.9678)
  line L24 (-26.0527, -226.7462) -> (-26.0527, 73.7538)
  line L25 (106.1913, -231.9602) -> (-20.8387, -231.9602)
  line L26 (111.4053, 73.7538) -> (111.4053, -226.7462)
  arc A1 centre (102.2613, 76.5802) radius 1.27 clockwise from (102.2613, 77.8502) to (103.5313, 76.5802)
  arc A2 centre (107.3413, 74.9038) radius 3.81 clockwise from (107.3413, 71.0938) to (103.5313, 74.9038)
  arc A3 centre (109.0177, 69.8238) radius 1.27 clockwise from (109.0177, 71.0938) to (110.2877, 69.8238)
  arc A4 centre (109.0177, -133.1662) radius 1.27 clockwise from (110.2877, -133.1662) to (109.0177, -134.4362)
  arc A5 centre (107.3413, -138.2462) radius 3.81 clockwise from (107.3413, -142.0562) to (107.3413, -134.4362)
  arc A6 centre (109.0177, -143.3262) radius 1.27 clockwise from (109.0177, -142.0562) to (110.2877, -143.3262)
  arc A7 centre (109.0177, -222.8162) radius 1.27 clockwise from (110.2877, -222.8162) to (109.0177, -224.0862)
  arc A8 centre (107.3413, -227.8962) radius 3.81 clockwise from (103.5313, -227.8962) to (107.3413, -224.0862)
  arc A9 centre (102.2613, -229.5726) radius 1.27 clockwise from (103.5313, -229.5726) to (102.2613, -230.8426)
  arc A10 centre (-16.9087, -229.5726) radius 1.27 clockwise from (-16.9087, -230.8426) to (-18.1787, -229.5726)
  arc A11 centre (-21.9887, -227.8962) radius 3.81 clockwise from (-21.9887, -224.0862) to (-18.1787, -227.8962)
  arc A12 centre (-23.6651, -222.8162) radius 1.27 clockwise from (-23.6651, -224.0862) to (-24.9351, -222.8162)
  arc A13 centre (-23.6651, -143.3262) radius 1.27 clockwise from (-24.9351, -143.3262) to (-23.6651, -142.0562)
  arc A14 centre (-21.9887, -138.2462) radius 3.81 clockwise from (-21.9887, -134.4362) to (-21.9887, -142.0562)
  arc A15 centre (-23.6651, -133.1662) radius 1.27 clockwise from (-23.6651, -134.4362) to (-24.9351, -133.1662)
  arc A16 centre (-23.6651, 69.8238) radius 1.27 clockwise from (-24.9351, 69.8238) to (-23.6651, 71.0938)
  arc A17 centre (-21.9887, 74.9038) radius 3.81 clockwise from (-18.1787, 74.9038) to (-21.9887, 71.0938)
  arc A18 centre (-16.9087, 76.5802) radius 1.27 clockwise from (-18.1787, 76.5802) to (-16.9087, 77.8502)
  circle C1 centre (-21.9887, -227.8962) radius 1.27
  circle C2 centre (-21.9887, -138.2462) radius 1.27
  circle C3 centre (-21.9887, 74.9038) radius 1.27
  arc A19 centre (-20.8387, 73.7538) radius 5.214 clockwise from (-26.0527, 73.7538) to (-20.8387, 78.9678)
  arc A20 centre (-20.8387, -226.7462) radius 5.214 clockwise from (-20.8387, -231.9602) to (-26.0527, -226.7462)
  arc A21 centre (106.1913, -226.7462) radius 5.214 clockwise from (111.4053, -226.7462) to (106.1913, -231.9602)
  arc A22 centre (106.1913, 73.7538) radius 5.214 clockwise from (106.1913, 78.9678) to (111.4053, 73.7538)
  circle C4 centre (107.3413, -227.8962) radius 1.27
  circle C5 centre (107.3413, -138.2462) radius 1.27
  arc A23 centre (107.5413, 74.9038) radius 1.27 clockwise from (107.4413, 73.6377) to (107.4413, 76.1698)
  arc A24 centre (107.3413, 74.9038) radius 1.27 clockwise from (107.4413, 76.1698) to (107.4413, 73.6377)
sketch "Sketch175" plane through (0, 74.3239, 0) normal (0, -1, 0) x axis (1, 0, 0)
  line L1 (102.2613, 77.8502) -> (-16.9087, 77.8502)
  line L2 (103.5313, 74.9038) -> (103.5313, 76.5802)
  line L3 (109.0177, 71.0938) -> (107.3413, 71.0938)
  line L4 (110.2877, -133.1662) -> (110.2877, 69.8238)
  line L5 (107.3413, -134.4362) -> (109.0177, -134.4362)
  line L6 (109.0177, -142.0562) -> (107.3413, -142.0562)
  line L7 (110.2877, -222.8162) -> (110.2877, -143.3262)
  line L8 (107.3413, -224.0862) -> (109.0177, -224.0862)
  line L9 (103.5313, -229.5726) -> (103.5313, -227.8962)
  line L10 (-16.9087, -230.8426) -> (102.2613, -230.8426)
  line L11 (-18.1787, -227.8962) -> (-18.1787, -229.5726)
  line L12 (-23.6651, -224.0862) -> (-21.9887, -224.0862)
  line L13 (-24.9351, -143.3262) -> (-24.9351, -222.8162)
  line L14 (-21.9887, -142.0562) -> (-23.6651, -142.0562)
  line L15 (-23.6651, -134.4362) -> (-21.9887, -134.4362)
  line L16 (-24.9351, 22.1988) -> (-24.9351, -133.1662)
  line L17 (-23.2587, 22.1988) -> (-24.9351, 22.1988)
  line L18 (-23.2587, 55.8538) -> (-23.2587, 22.1988)
  line L19 (-24.9351, 55.8538) -> (-23.2587, 55.8538)
  line L20 (-24.9351, 69.8238) -> (-24.9351, 55.8538)
  line L21 (-21.9887, 71.0938) -> (-23.6651, 71.0938)
  line L22 (-18.1787, 76.5802) -> (-18.1787, 74.9038)
  line L23 (-20.8387, 78.9678) -> (106.1913, 78.9678)
  line L24 (-26.0527, -226.7462) -> (-26.0527, 73.7538)
  line L25 (106.1913, -231.9602) -> (-20.8387, -231.9602)
  line L26 (111.4053, 73.7538) -> (111.4053, -226.7462)
  line L27 (110.2877, -133.1662) -> (-24.9351, -133.1662)
  line L28 (110.2877, -152.7649) -> (110.2877, -133.1662)
  line L29 (-24.9351, -152.7649) -> (110.2877, -152.7649)
  line L30 (-24.9351, -133.1662) -> (-24.9351, -152.7649)
  arc A1 centre (102.2613, 76.5802) radius 1.27 clockwise from (102.2613, 77.8502) to (103.5313, 76.5802)
  arc A2 centre (107.3413, 74.9038) radius 3.81 clockwise from (107.3413, 71.0938) to (103.5313, 74.9038)
  arc A3 centre (109.0177, 69.8238) radius 1.27 clockwise from (109.0177, 71.0938) to (110.2877, 69.8238)
  arc A4 centre (109.0177, -133.1662) radius 1.27 clockwise from (110.2877, -133.1662) to (109.0177, -134.4362)
  arc A5 centre (107.3413, -138.2462) radius 3.81 clockwise from (107.3413, -142.0562) to (107.3413, -134.4362)
  arc A6 centre (109.0177, -143.3262) radius 1.27 clockwise from (109.0177, -142.0562) to (110.2877, -143.3262)
  arc A7 centre (109.0177, -222.8162) radius 1.27 clockwise from (110.2877, -222.8162) to (109.0177, -224.0862)
  arc A8 centre (107.3413, -227.8962) radius 3.81 clockwise from (103.5313, -227.8962) to (107.3413, -224.0862)
  arc A9 centre (102.2613, -229.5726) radius 1.27 clockwise from (103.5313, -229.5726) to (102.2613, -230.8426)
  arc A10 centre (-16.9087, -229.5726) radius 1.27 clockwise from (-16.9087, -230.8426) to (-18.1787, -229.5726)
  arc A11 centre (-21.9887, -227.8962) radius 3.81 clockwise from (-21.9887, -224.0862) to (-18.1787, -227.8962)
  arc A12 centre (-23.6651, -222.8162) radius 1.27 clockwise from (-23.6651, -224.0862) to (-24.9351, -222.8162)
  arc A13 centre (-23.6651, -143.3262) radius 1.27 clockwise from (-24.9351, -143.3262) to (-23.6651, -142.0562)
  arc A14 centre (-21.9887, -138.2462) radius 3.81 clockwise from (-21.9887, -134.4362) to (-21.9887, -142.0562)
  arc A15 centre (-23.6651, -133.1662) radius 1.27 clockwise from (-23.6651, -134.4362) to (-24.9351, -133.1662)
  arc A16 centre (-23.6651, 69.8238) radius 1.27 clockwise from (-24.9351, 69.8238) to (-23.6651, 71.0938)
  arc A17 centre (-21.9887, 74.9038) radius 3.81 clockwise from (-18.1787, 74.9038) to (-21.9887, 71.0938)
  arc A18 centre (-16.9087, 76.5802) radius 1.27 clockwise from (-18.1787, 76.5802) to (-16.9087, 77.8502)
  circle C1 centre (-21.9887, -227.8962) radius 1.27
  circle C2 centre (-21.9887, -138.2462) radius 1.27
  circle C3 centre (-21.9887, 74.9038) radius 1.27
  arc A19 centre (-20.8387, 73.7538) radius 5.214 clockwise from (-26.0527, 73.7538) to (-20.8387, 78.9678)
  arc A20 centre (-20.8387, -226.7462) radius 5.214 clockwise from (-20.8387, -231.9602) to (-26.0527, -226.7462)
  arc A21 centre (106.1913, -226.7462) radius 5.214 clockwise from (111.4053, -226.7462) to (106.1913, -231.9602)
  arc A22 centre (106.1913, 73.7538) radius 5.214 clockwise from (106.1913, 78.9678) to (111.4053, 73.7538)
  circle C4 centre (107.3413, -227.8962) radius 1.27
  circle C5 centre (107.3413, -138.2462) radius 1.27
  arc A23 centre (107.5413, 74.9038) radius 1.27 clockwise from (107.4413, 73.6377) to (107.4413, 76.1698)
  arc A24 centre (107.3413, 74.9038) radius 1.27 clockwise from (107.4413, 76.1698) to (107.4413, 73.6377)
  point P77 (110.2877, -152.7649)
  point P46 (-24.9351, -133.1662)
  point P75 (-24.9351, -133.1662)
  horizontal L27
  vertical L28
  horizontal L29
  vertical L30
  coincident L7 P77
  coincident P46 P75
extrude "Extrude56" new body sketch "Sketch175" profile of A4 L5 A5 L6 A6 A13 L14 A14 L15 A15 C2 C5 L28 L30 against normal blind 10.5
copy_paste_bodies "CopyPasteBodies7"
move "Move19"
move "Move20"
move "Move21"
move "Move22"
move "Move23"
move "Move24"
move "Move25"
combine "Combine5"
